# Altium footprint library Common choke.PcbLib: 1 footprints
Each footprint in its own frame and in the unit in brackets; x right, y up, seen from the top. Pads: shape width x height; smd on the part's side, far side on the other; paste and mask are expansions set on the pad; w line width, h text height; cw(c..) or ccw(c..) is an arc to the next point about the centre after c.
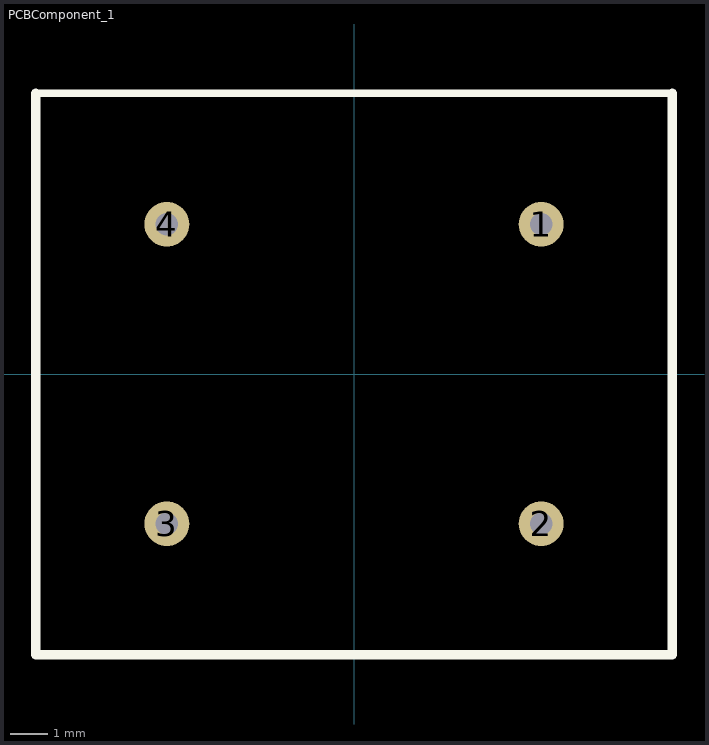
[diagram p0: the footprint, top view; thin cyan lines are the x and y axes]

## PCBComponent_1 [mm]
pads (4):
  round 1.2 hole 0.6: 1(5,4) 2(5,-4) 3(-5,-4) 4(-5,4)
Top Overlay:
  lines w0.2: -8.5,7.5 8.5,7.5
  lines w0.254: -8.5,7.5 -8.5,-7.5 8.5,-7.5 8.5,7.5
M5 Assembly Top:
  text ".Designator" at -2,-0.7 h1.85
